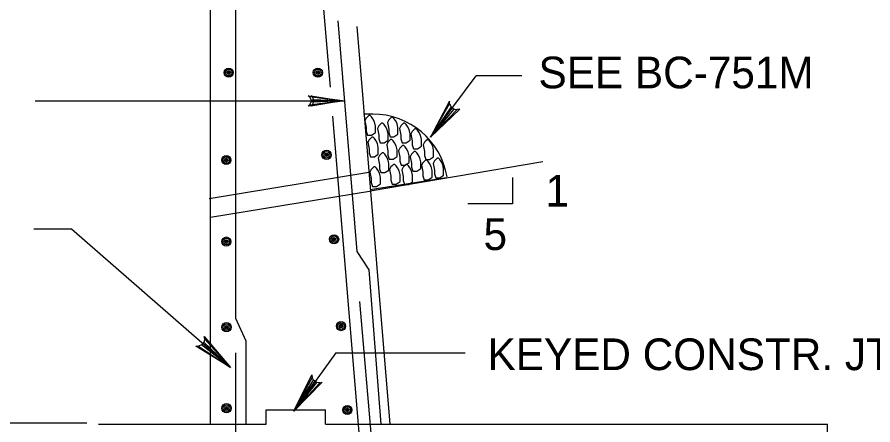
# Model space of a CAD drawing. Extents: x 639011 to 639866, y 298840 to 300028.
# Drawn here: x 639301.8 to 639383, y 299537.2 to 299575.8 of the extents above; entities that cross this region are included whole.
import ezdxf

# ---------------------------------------------------------------- set-up
doc = ezdxf.new("R2010")
doc.units = 0
doc.layers.add('2', color=7, linetype='Continuous')

msp = doc.modelspace()

# ---------------------------------------------------------------- linework, layer by layer
at = {"layer": '2'}
for p, q in [((639320.178, 299537.217), (639320.178, 299645.717)), ((639322.553, 299547.217), (639322.553, 299645.092)), ((639330.303, 299583.592), (639331.506, 299569.156)), ((639332.233, 299575.435), (639334.053, 299553.592)), ((639334.052, 299574.899), (639337.178, 299537.217)), ((639341.021, 299564.411), (639345.362, 299570.213)), ((639349.676, 299570.213), (639345.362, 299570.213)), ((639303.553, 299567.842), (639332.865, 299567.842)), ((639342.826, 299567.809), (639341.021, 299564.411)), ((639341.021, 299564.411), (639342.839, 299567.559)), ((639342.969, 299567.292), (639341.021, 299564.411)), ((639341.021, 299564.411), (639343.114, 299567.182)), ((639341.021, 299564.411), (639343.258, 299567.073)), ((639341.021, 299564.411), (639343.802, 299567.069)), ((639343.544, 299567.018), (639341.021, 299564.411)), ((639342.839, 299567.559), (639342.826, 299567.809)), ((639342.839, 299567.559), (639342.969, 299567.292)), ((639342.969, 299567.292), (639343.258, 299567.073)), ((639343.258, 299567.073), (639343.544, 299567.018)), ((639343.802, 299567.069), (639343.544, 299567.018)), ((639331.736, 299566.393), (639334.86, 299528.911)), ((639335.303, 299559.342), (639351.678, 299562.092)), ((639320.053, 299558.592), (639335.178, 299561.092)), ((639335.303, 299559.467), (639342.553, 299560.592)), ((639348.803, 299560.592), (639348.803, 299558.092)), ((639320.178, 299556.842), (639335.428, 299559.342)), ((639335.553, 299559.342), (639335.553, 299559.342)), ((639335.553, 299559.342), (639335.553, 299559.342)), ((639348.803, 299558.092), (639344.553, 299558.092)), ((639303.402, 299555.716), (639306.984, 299555.716)), ((639306.984, 299555.716), (639322.053, 299542.592)), ((639334.053, 299553.592), (639335.178, 299551.842)), ((639335.178, 299551.842), (639336.303, 299537.217)), ((639334.303, 299548.842), (639336.053, 299528.092)), ((639323.553, 299545.092), (639322.553, 299547.217)), ((639323.553, 299545.092), (639322.553, 299547.217)), ((639319.614, 299545.287), (639319.542, 299544.998)), ((639319.614, 299545.287), (639319.574, 299545.534)), ((639319.574, 299545.534), (639322.053, 299542.592)), ((639322.053, 299542.592), (639319.614, 299545.287)), ((639318.775, 299544.606), (639319.039, 299544.61)), ((639322.053, 299542.592), (639318.775, 299544.606)), ((639319.307, 299544.724), (639319.039, 299544.61)), ((639319.039, 299544.61), (639322.053, 299542.592)), ((639319.542, 299544.998), (639319.307, 299544.724)), ((639322.053, 299542.592), (639319.307, 299544.724)), ((639322.053, 299542.592), (639319.424, 299544.861)), ((639319.542, 299544.998), (639322.053, 299542.592)), ((639323.553, 299537.217), (639323.553, 299545.092)), ((639323.553, 299537.217), (639323.553, 299545.092)), ((639322.553, 299525.592), (639322.553, 299543.967)), ((639332.053, 299543.967), (639328.053, 299538.467)), ((639332.053, 299543.967), (639344.303, 299543.967)), ((639328.053, 299538.467), (639329.772, 299541.909)), ((639329.772, 299541.909), (639329.799, 299541.646)), ((639329.799, 299541.646), (639328.053, 299538.467)), ((639328.053, 299538.467), (639329.936, 299541.389)), ((639328.053, 299538.467), (639330.083, 299541.284)), ((639330.766, 299541.194), (639328.053, 299538.467)), ((639330.23, 299541.178), (639328.053, 299538.467)), ((639328.053, 299538.467), (639330.524, 299541.133)), ((639329.936, 299541.389), (639329.799, 299541.646)), ((639330.23, 299541.178), (639329.936, 299541.389)), ((639330.524, 299541.133), (639330.23, 299541.178)), ((639330.524, 299541.133), (639330.766, 299541.194)), ((639325.428, 299538.592), (639331.053, 299538.592)), ((639325.428, 299537.217), (639325.428, 299538.592)), ((639331.053, 299537.217), (639331.053, 299538.592)), ((639266.178, 299537.342), (639308.428, 299537.342)), ((639309.553, 299537.217), (639325.428, 299537.217)), ((639331.053, 299537.217), (639378.678, 299537.217)), ((639378.678, 299523.967), (639378.678, 299537.217))]:
    msp.add_line(p, q, dxfattribs=at)
for points in [[(639329.553, 299568.217), (639329.678, 299567.967), (639332.428, 299567.842), (639329.553, 299568.217), (639329.428, 299568.342), (639332.428, 299567.842), (639329.678, 299567.717), (639329.553, 299567.467), (639332.428, 299567.842), (639329.428, 299567.342), (639329.553, 299567.467)], [(639329.806, 299568.217), (639329.931, 299567.967), (639332.681, 299567.842), (639329.806, 299568.217), (639329.681, 299568.342), (639332.681, 299567.842), (639329.931, 299567.717), (639329.806, 299567.467), (639332.681, 299567.842), (639329.681, 299567.342), (639329.806, 299567.467)], [(639335.553, 299566.592), (639335.303, 299566.592), (639335.053, 299566.592), (639334.678, 299566.592)], [(639335.428, 299566.342), (639335.303, 299566.467), (639335.178, 299566.467), (639335.053, 299566.342), (639334.928, 299566.217), (639334.803, 299565.967), (639334.928, 299565.342), (639334.928, 299564.967), (639335.053, 299564.592), (639335.428, 299564.592), (639335.803, 299564.842), (639335.803, 299565.092), (639335.803, 299565.467), (639335.719, 299565.862), (639335.56, 299566.151), (639335.428, 299566.342)], [(639337.561, 299566.183), (639337.436, 299566.308), (639337.311, 299566.308), (639337.186, 299566.183), (639337.061, 299566.058), (639336.936, 299565.808), (639337.061, 299565.183), (639337.061, 299564.808), (639337.186, 299564.433), (639337.561, 299564.433), (639337.936, 299564.683), (639337.936, 299564.933), (639337.936, 299565.308), (639337.852, 299565.703), (639337.693, 299565.992), (639337.561, 299566.183)], [(639336.63, 299565.615), (639336.505, 299565.74), (639336.38, 299565.74), (639336.255, 299565.615), (639336.13, 299565.49), (639336.005, 299565.24), (639336.13, 299564.615), (639336.13, 299564.24), (639336.255, 299563.865), (639336.63, 299563.865), (639337.005, 299564.115), (639337.005, 299564.365), (639337.005, 299564.74), (639336.921, 299565.135), (639336.763, 299565.425), (639336.63, 299565.615)], [(639338.718, 299565.615), (639338.593, 299565.74), (639338.468, 299565.74), (639338.343, 299565.615), (639338.218, 299565.49), (639338.093, 299565.24), (639338.218, 299564.615), (639338.218, 299564.24), (639338.343, 299563.865), (639338.718, 299563.865), (639339.093, 299564.115), (639339.093, 299564.365), (639339.093, 299564.74), (639339.009, 299565.135), (639338.85, 299565.425), (639338.718, 299565.615)], [(639339.785, 299565.07), (639339.66, 299565.195), (639339.535, 299565.195), (639339.41, 299565.07), (639339.285, 299564.945), (639339.16, 299564.695), (639339.285, 299564.07), (639339.285, 299563.695), (639339.41, 299563.32), (639339.785, 299563.32), (639340.16, 299563.57), (639340.16, 299563.82), (639340.16, 299564.195), (639340.076, 299564.59), (639339.917, 299564.88), (639339.785, 299565.07)], [(639335.7, 299564.298), (639335.575, 299564.423), (639335.45, 299564.423), (639335.325, 299564.298), (639335.2, 299564.173), (639335.075, 299563.923), (639335.2, 299563.298), (639335.2, 299562.923), (639335.325, 299562.548), (639335.7, 299562.548), (639336.075, 299562.798), (639336.075, 299563.048), (639336.075, 299563.423), (639335.991, 299563.818), (639335.832, 299564.108), (639335.7, 299564.298)], [(639337.493, 299564.071), (639337.368, 299564.196), (639337.243, 299564.196), (639337.118, 299564.071), (639336.993, 299563.946), (639336.868, 299563.696), (639336.993, 299563.071), (639336.993, 299562.696), (639337.118, 299562.321), (639337.493, 299562.321), (639337.868, 299562.571), (639337.868, 299562.821), (639337.868, 299563.196), (639337.784, 299563.591), (639337.625, 299563.881), (639337.493, 299564.071)], [(639340.942, 299564.049), (639340.817, 299564.174), (639340.692, 299564.174), (639340.567, 299564.049), (639340.442, 299563.924), (639340.317, 299563.674), (639340.442, 299563.049), (639340.442, 299562.674), (639340.567, 299562.299), (639340.942, 299562.299), (639341.317, 299562.549), (639341.317, 299562.799), (639341.317, 299563.174), (639341.233, 299563.568), (639341.074, 299563.858), (639340.942, 299564.049)], [(639338.628, 299563.504), (639338.503, 299563.629), (639338.378, 299563.629), (639338.253, 299563.504), (639338.128, 299563.379), (639338.003, 299563.129), (639338.128, 299562.504), (639338.128, 299562.129), (639338.253, 299561.754), (639338.628, 299561.754), (639339.003, 299562.004), (639339.003, 299562.254), (639339.003, 299562.629), (639338.918, 299563.024), (639338.76, 299563.313), (639338.628, 299563.504)], [(639339.717, 299562.936), (639339.592, 299563.061), (639339.467, 299563.061), (639339.342, 299562.936), (639339.217, 299562.811), (639339.092, 299562.561), (639339.217, 299561.936), (639339.217, 299561.561), (639339.342, 299561.186), (639339.717, 299561.186), (639340.092, 299561.436), (639340.092, 299561.686), (639340.092, 299562.061), (639340.008, 299562.456), (639339.849, 299562.746), (639339.717, 299562.936)], [(639336.699, 299562.8), (639336.574, 299562.925), (639336.449, 299562.925), (639336.324, 299562.8), (639336.199, 299562.675), (639336.074, 299562.425), (639336.199, 299561.8), (639336.199, 299561.425), (639336.324, 299561.05), (639336.699, 299561.05), (639337.074, 299561.3), (639337.074, 299561.55), (639337.074, 299561.925), (639336.99, 299562.32), (639336.831, 299562.609), (639336.699, 299562.8)], [(639340.806, 299562.119), (639340.681, 299562.244), (639340.556, 299562.244), (639340.431, 299562.119), (639340.306, 299561.994), (639340.181, 299561.744), (639340.306, 299561.119), (639340.306, 299560.744), (639340.431, 299560.369), (639340.806, 299560.369), (639341.181, 299560.619), (639341.181, 299560.869), (639341.181, 299561.244), (639341.097, 299561.639), (639340.938, 299561.928), (639340.806, 299562.119)], [(639341.895, 299562.3), (639341.77, 299562.425), (639341.645, 299562.425), (639341.52, 299562.3), (639341.395, 299562.175), (639341.27, 299561.925), (639341.395, 299561.3), (639341.395, 299560.925), (639341.52, 299560.55), (639341.895, 299560.55), (639342.27, 299560.8), (639342.27, 299561.05), (639342.27, 299561.425), (639342.186, 299561.82), (639342.027, 299562.11), (639341.895, 299562.3)], [(639335.904, 299561.483), (639335.779, 299561.608), (639335.654, 299561.608), (639335.529, 299561.483), (639335.404, 299561.358), (639335.279, 299561.108), (639335.404, 299560.483), (639335.404, 299560.108), (639335.529, 299559.733), (639335.904, 299559.733), (639336.279, 299559.983), (639336.279, 299560.233), (639336.279, 299560.608), (639336.195, 299561.003), (639336.036, 299561.292), (639335.904, 299561.483)], [(639337.765, 299561.71), (639337.64, 299561.835), (639337.515, 299561.835), (639337.39, 299561.71), (639337.265, 299561.585), (639337.14, 299561.335), (639337.265, 299560.71), (639337.265, 299560.335), (639337.39, 299559.96), (639337.765, 299559.96), (639338.14, 299560.21), (639338.14, 299560.46), (639338.14, 299560.835), (639338.056, 299561.23), (639337.897, 299561.519), (639337.765, 299561.71)], [(639338.945, 299561.687), (639338.82, 299561.812), (639338.695, 299561.812), (639338.57, 299561.687), (639338.445, 299561.562), (639338.32, 299561.312), (639338.445, 299560.687), (639338.445, 299560.312), (639338.57, 299559.937), (639338.945, 299559.937), (639339.32, 299560.187), (639339.32, 299560.437), (639339.32, 299560.812), (639339.236, 299561.207), (639339.077, 299561.497), (639338.945, 299561.687)]]:
    msp.add_lwpolyline(points, dxfattribs=at)
for centre, radius in [((639321.888, 299570.524), 0.437), ((639321.888, 299570.524), 0.437), ((639321.888, 299570.524), 0.312), ((639321.888, 299570.524), 0.312), ((639321.888, 299570.524), 0.17), ((639321.888, 299570.524), 0.17), ((639321.888, 299570.524), 0.086), ((639321.888, 299570.524), 0.086), ((639321.888, 299570.524), 0.0368), ((639321.888, 299570.524), 0.0368), ((639330.344, 299570.524), 0.437), ((639330.344, 299570.524), 0.437), ((639330.344, 299570.524), 0.312), ((639330.344, 299570.524), 0.312), ((639330.344, 299570.524), 0.17), ((639330.344, 299570.524), 0.17), ((639330.344, 299570.524), 0.086), ((639330.344, 299570.524), 0.086), ((639330.344, 299570.524), 0.0368), ((639330.344, 299570.524), 0.0368), ((639331.167, 299562.739), 0.437), ((639331.167, 299562.739), 0.437), ((639331.167, 299562.739), 0.312), ((639331.167, 299562.739), 0.312), ((639321.668, 299562.246), 0.437), ((639321.668, 299562.246), 0.437), ((639321.668, 299562.246), 0.312), ((639321.668, 299562.246), 0.312), ((639321.668, 299562.246), 0.17), ((639321.668, 299562.246), 0.17), ((639321.668, 299562.246), 0.086), ((639321.668, 299562.246), 0.086), ((639321.668, 299562.246), 0.0368), ((639321.668, 299562.246), 0.0368), ((639331.167, 299562.739), 0.17), ((639331.167, 299562.739), 0.17), ((639331.167, 299562.739), 0.086), ((639331.167, 299562.739), 0.086), ((639331.167, 299562.739), 0.0368), ((639331.167, 299562.739), 0.0368), ((639321.668, 299554.517), 0.437), ((639321.668, 299554.517), 0.437), ((639331.88, 299554.736), 0.437), ((639331.88, 299554.736), 0.437), ((639331.88, 299554.736), 0.312), ((639331.88, 299554.736), 0.312), ((639331.88, 299554.736), 0.17), ((639331.88, 299554.736), 0.17), ((639321.668, 299554.517), 0.312), ((639321.668, 299554.517), 0.312), ((639321.668, 299554.517), 0.17), ((639321.668, 299554.517), 0.17), ((639321.668, 299554.517), 0.086), ((639321.668, 299554.517), 0.086), ((639321.668, 299554.517), 0.0368), ((639321.668, 299554.517), 0.0368), ((639331.88, 299554.736), 0.086), ((639331.88, 299554.736), 0.086), ((639331.88, 299554.736), 0.0368), ((639331.88, 299554.736), 0.0368), ((639321.683, 299546.404), 0.437), ((639321.683, 299546.404), 0.437), ((639332.537, 299546.514), 0.437), ((639332.537, 299546.514), 0.437), ((639332.537, 299546.514), 0.312), ((639332.537, 299546.514), 0.312), ((639321.683, 299546.404), 0.312), ((639321.683, 299546.404), 0.312), ((639321.683, 299546.404), 0.17), ((639321.683, 299546.404), 0.17), ((639321.683, 299546.404), 0.086), ((639321.683, 299546.404), 0.086), ((639321.683, 299546.404), 0.0368), ((639321.683, 299546.404), 0.0368), ((639332.537, 299546.514), 0.17), ((639332.537, 299546.514), 0.17), ((639332.537, 299546.514), 0.086), ((639332.537, 299546.514), 0.086), ((639332.537, 299546.514), 0.0368), ((639332.537, 299546.514), 0.0368), ((639321.683, 299538.729), 0.437), ((639321.683, 299538.729), 0.437), ((639321.683, 299538.729), 0.312), ((639321.683, 299538.729), 0.312), ((639321.683, 299538.729), 0.17), ((639321.683, 299538.729), 0.17), ((639321.683, 299538.729), 0.086), ((639321.683, 299538.729), 0.086), ((639321.683, 299538.729), 0.0368), ((639321.683, 299538.729), 0.0368), ((639333.14, 299538.565), 0.437), ((639333.14, 299538.565), 0.437), ((639333.14, 299538.565), 0.312), ((639333.14, 299538.565), 0.312), ((639333.14, 299538.565), 0.17), ((639333.14, 299538.565), 0.17), ((639333.14, 299538.565), 0.086), ((639333.14, 299538.565), 0.086), ((639333.14, 299538.565), 0.0368), ((639333.14, 299538.565), 0.0368)]:
    msp.add_circle(centre, radius, dxfattribs=at)
msp.add_arc((639335.554, 299559.456), 7.143, 9.58494, 90, dxfattribs=at)

# ---------------------------------------------------------------- texts
for s, p in [('SEE BC-751M', (639351.265, 299569.04)), ('1', (639351.928, 299557.842)), ('5', (639346.053, 299553.717)), ('KEYED CONSTR. JT.', (639346.428, 299542.342))]:
    msp.add_text(s, height=3, dxfattribs=at).set_placement(p)

doc.saveas('drawing.dxf')
